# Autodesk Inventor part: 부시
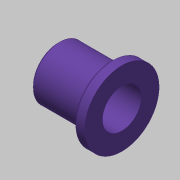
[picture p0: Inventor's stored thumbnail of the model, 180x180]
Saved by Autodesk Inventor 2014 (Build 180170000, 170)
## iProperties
Created: 2019-10
Part Number: 부시
Material: 강철, 연강
Document SubType Name: Modeling
Designer: mduedu
Density: 1 g/cm^3
Appearance: Violet
Author: mduedu
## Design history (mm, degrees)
sketch "스케치1"
  geometry: L1 (0, 0)-(-18, 0); L2 (0, -5.5)-(0, -10.5); L3 (0, -10.5)-(-3, -10.5); L4 (-3, -10.5)-(-3, -7.5); L5 (-3, -7.5)-(-18, -7.5); L6 (-18, -7.5)-(-18, -5.5); L7 (-18, -5.5)-(0, -5.5)
  constraints: 14 end point, 3 parallel, 2 horizontal, 2 perpendicular, 2 vertical alignment
  dimensions: "d0" = 18 distance of L1.start L1.end; "d1" = 11 diameter of L7 L1; "d2" = 15 diameter of L5 L1; "d3" = 21 diameter of L3 L1; "d4" = 3 distance of L2.end L3.end
revolve "회전1" sketch "스케치1" stored, may be unused: angle "d5" = 90 deg
chamfer "모따기1" distance "d6" = 0.5; stored, may be unused: second distance "d7" = 2, angle "d8" = 45 deg
chamfer "모따기2" distance "d9" = 0.5; stored, may be unused: second distance "d10" = 2, angle "d11" = 45 deg
node "솔리드1"
